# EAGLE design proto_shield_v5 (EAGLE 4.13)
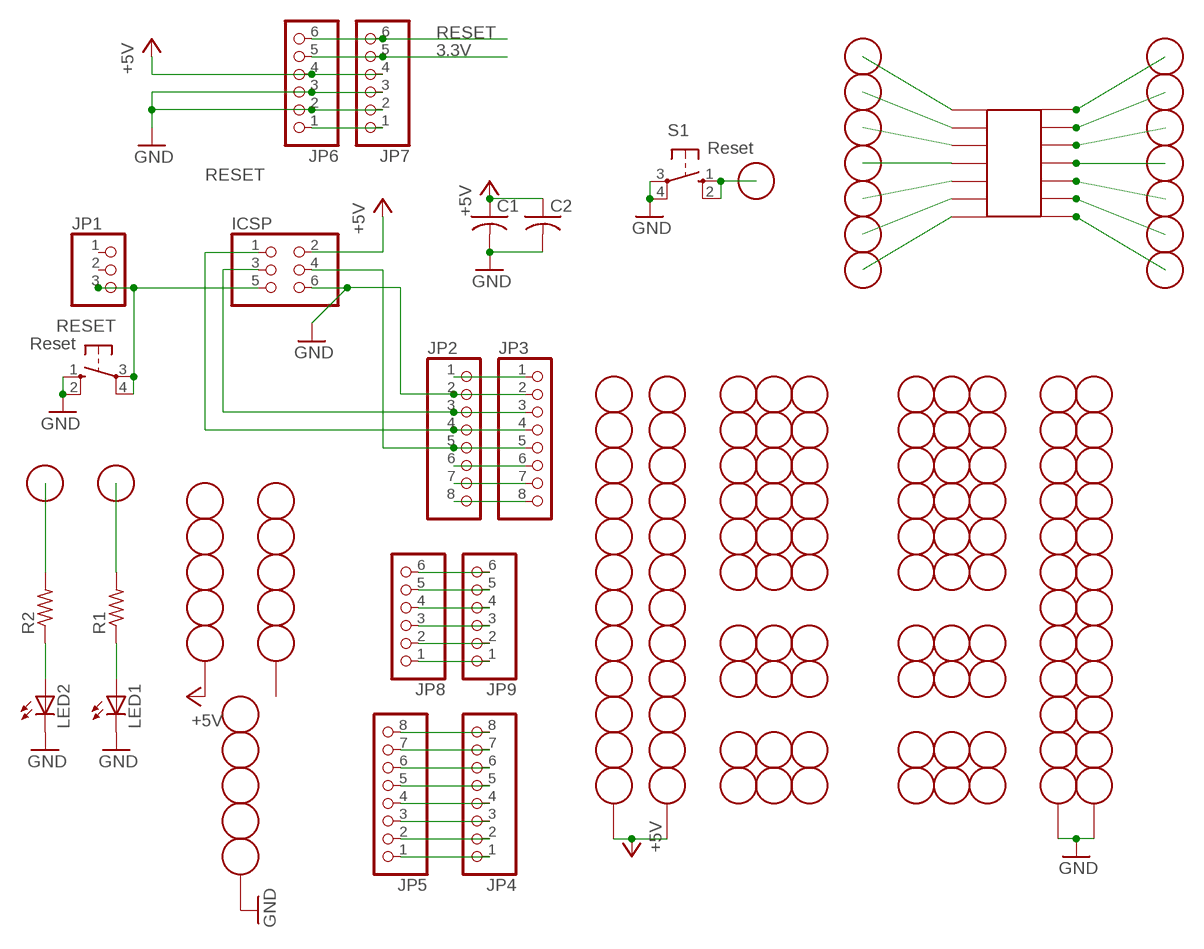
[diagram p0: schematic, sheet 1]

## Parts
C1  C-US025-025X050  [C025-025X050]
C2  C-US025-025X050  [C025-025X050]
GNDSTRIP1  12-STRIP  [12-STRIP]
GNDSTRIP2  12-STRIP  [12-STRIP]
IC1  SMD-14  [SO-14NMW]
ICSP  PINHD-2X3  [2X03]
JP1  PINHD-1X3CB  [1X03-CLEANBIG]
JP2  PINHD-1X8B  [1X08-BIG]
JP3  PINHD-1X8CLEANBIG  [1X08-CLEANBIG]
JP4  PINHD-1X8B  [1X08-BIG]
JP5  PINHD-1X8CLEANBIG  [1X08-CLEANBIG]
JP6  PINHD-1X6CB  [1X06-CLEANBIG]
JP7  PINHD-1X6B  [1X06-BIG]
JP8  PINHD-1X6CB  [1X06-CLEANBIG]
JP9  PINHD-1X6B  [1X06-BIG]
LED1  LED3MM  [LED3MM]
LED2  LED3MM  [LED3MM]
R1  R-US_0207/5V  [0207/5V]
R2  R-US_0207/5V  [0207/5V]
RESET  Reset  10-XX  [B3F-10XX]
S1  Reset  10-XX  [B3F-10XX]
U$1  5-STRIP  [5-STRIP]
U$2  PERF  [PERFHOLE]
U$4  PERF  [PERFHOLE]
U$5  3-STRIP  [3-STRIP]
U$6  PERF  [PERFHOLE]
U$7  PERF  [PERFHOLE]
U$8  PERF  [PERFHOLE]
U$9  PERF  [PERFHOLE]
U$10  3-STRIP  [3-STRIP]
U$11  3-STRIP  [3-STRIP]
U$12  3-STRIP  [3-STRIP]
U$13  3-STRIP  [3-STRIP]
U$14  3-STRIP  [3-STRIP]
U$15  3-STRIP  [3-STRIP]
U$16  PERF  [PERFHOLE]
U$17  3-STRIP  [3-STRIP]
U$18  3-STRIP  [3-STRIP]
U$19  PERF  [PERFHOLE]
U$20  3-STRIP  [3-STRIP]
U$21  3-STRIP  [3-STRIP]
U$22  3-STRIP  [3-STRIP]
U$23  3-STRIP  [3-STRIP]
U$25  PERF  [PERFHOLE]
U$26  3-STRIP  [3-STRIP]
U$27  PERF  [PERFHOLE]
U$28  3-STRIP  [3-STRIP]
U$29  3-STRIP  [3-STRIP]
U$30  3-STRIP  [3-STRIP]
U$31  3-STRIP  [3-STRIP]
U$32  3-STRIP  [3-STRIP]
U$33  3-STRIP  [3-STRIP]
U$34  PERF  [PERFHOLE]
U$35  PERF  [PERFHOLE]
U$36  5-STRIP  [5-STRIP]
U$37  PERF  [PERFHOLE]
U$38  PERF  [PERFHOLE]
U$39  PERF  [PERFHOLE]
U$40  PERF  [PERFHOLE]
U$41  PERF  [PERFHOLE]
U$42  5-STRIP  [5-STRIP]
VCCSTRIP1  12-STRIP  [12-STRIP]
VCCSTRIP2  12-STRIP  [12-STRIP]

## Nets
3.3V: JP6.5 JP7.5
+5V: C1.1 C2.1 ICSP.2 JP6.4 JP7.4 U$36.P$3 VCCSTRIP1.P$1 VCCSTRIP2.P$1
GND: C1.2 C2.2 GNDSTRIP1.P$1 GNDSTRIP2.P$1 ICSP.6 JP2.2 JP3.2 JP6.2 JP6.3 JP7.2 JP7.3 LED1.K(C) LED2.K(C) RESET.1(S) RESET.2(S1) S1.3(P) S1.4(P1) U$42.P$3
N$2: ICSP.3 JP2.3 JP3.3
N$4: ICSP.1 JP2.4 JP3.4
N$5: ICSP.4 JP2.5 JP3.5
N$8: LED1.A R1.1
N$15: JP6.1 JP7.1
N$16: R1.2 U$7.P$1
N$40: R2.2 U$4.P$1
N$41: LED2.A R2.1
N$126: IC1.P$1 U$2.P$1
N$127: IC1.P$2 U$6.P$1
N$135: JP2.8 JP3.8
N$145: JP2.7 JP3.7
N$149: IC1.P$3 U$8.P$1
N$150: IC1.P$4 U$9.P$1
N$151: IC1.P$5 U$19.P$1
N$152: JP2.6 JP3.6
N$153: JP2.1 JP3.1
N$154: JP8.1 JP9.1
N$155: IC1.P$6 U$25.P$1
N$156: IC1.P$7 U$27.P$1
N$157: IC1.P$8 U$34.P$1
N$158: IC1.P$9 U$35.P$1
N$159: IC1.P$10 U$37.P$1
N$164: JP8.2 JP9.2
N$165: IC1.P$11 U$38.P$1
N$166: IC1.P$12 U$39.P$1
N$167: IC1.P$13 U$40.P$1
N$178: IC1.P$14 U$41.P$1
N$181: JP8.3 JP9.3
N$182: JP8.4 JP9.4
N$183: JP8.5 JP9.5
N$184: JP8.6 JP9.6
N$185: JP4.1 JP5.1
N$186: JP4.2 JP5.2
N$187: JP4.3 JP5.3
N$188: JP4.4 JP5.4
N$189: JP4.5 JP5.5
N$190: JP4.6 JP5.6
N$191: JP4.7 JP5.7
N$192: JP4.8 JP5.8
N$194: S1.1(S) S1.2(S1) U$16.P$1
RESET: ICSP.5 JP1.3 JP6.6 JP7.6 RESET.3(P) RESET.4(P1)
Unconnected: JP1.1 JP1.2 U$1.P$3

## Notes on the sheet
- RESET

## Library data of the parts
C1 C2 = rcl-ez:C-US: CAPACITOR, American symbol
GNDSTRIP1 GNDSTRIP2 VCCSTRIP1 VCCSTRIP2 = Atmex:12-STRIP
IC1 = carduino:SMD-14
ICSP = pinhead:PINHD-2X3: PIN HEADER
JP1 = carduino:PINHD-1X3: PIN HEADER
JP2-JP5 = carduino:PINHD-1X8: PIN HEADER
JP6-JP9 = carduino:PINHD-1X6: PIN HEADER
LED1 LED2 = minimidi:LED: LED
R1 R2 = rcl-ez:R-US_: RESISTOR, American symbol
RESET S1 = switch-omron:10-XX: OMRON SWITCH
U$1 U$36 U$42 = Atmex:5-STRIP
U$2 U$4 U$6-U$9 U$16 U$19 U$25 U$27 U$34 U$35 U$37-U$41 = carduino:PERF
U$5 U$10-U$15 U$17 U$18 U$20-U$23 U$26 U$28-U$33 = Atmex:3-STRIP

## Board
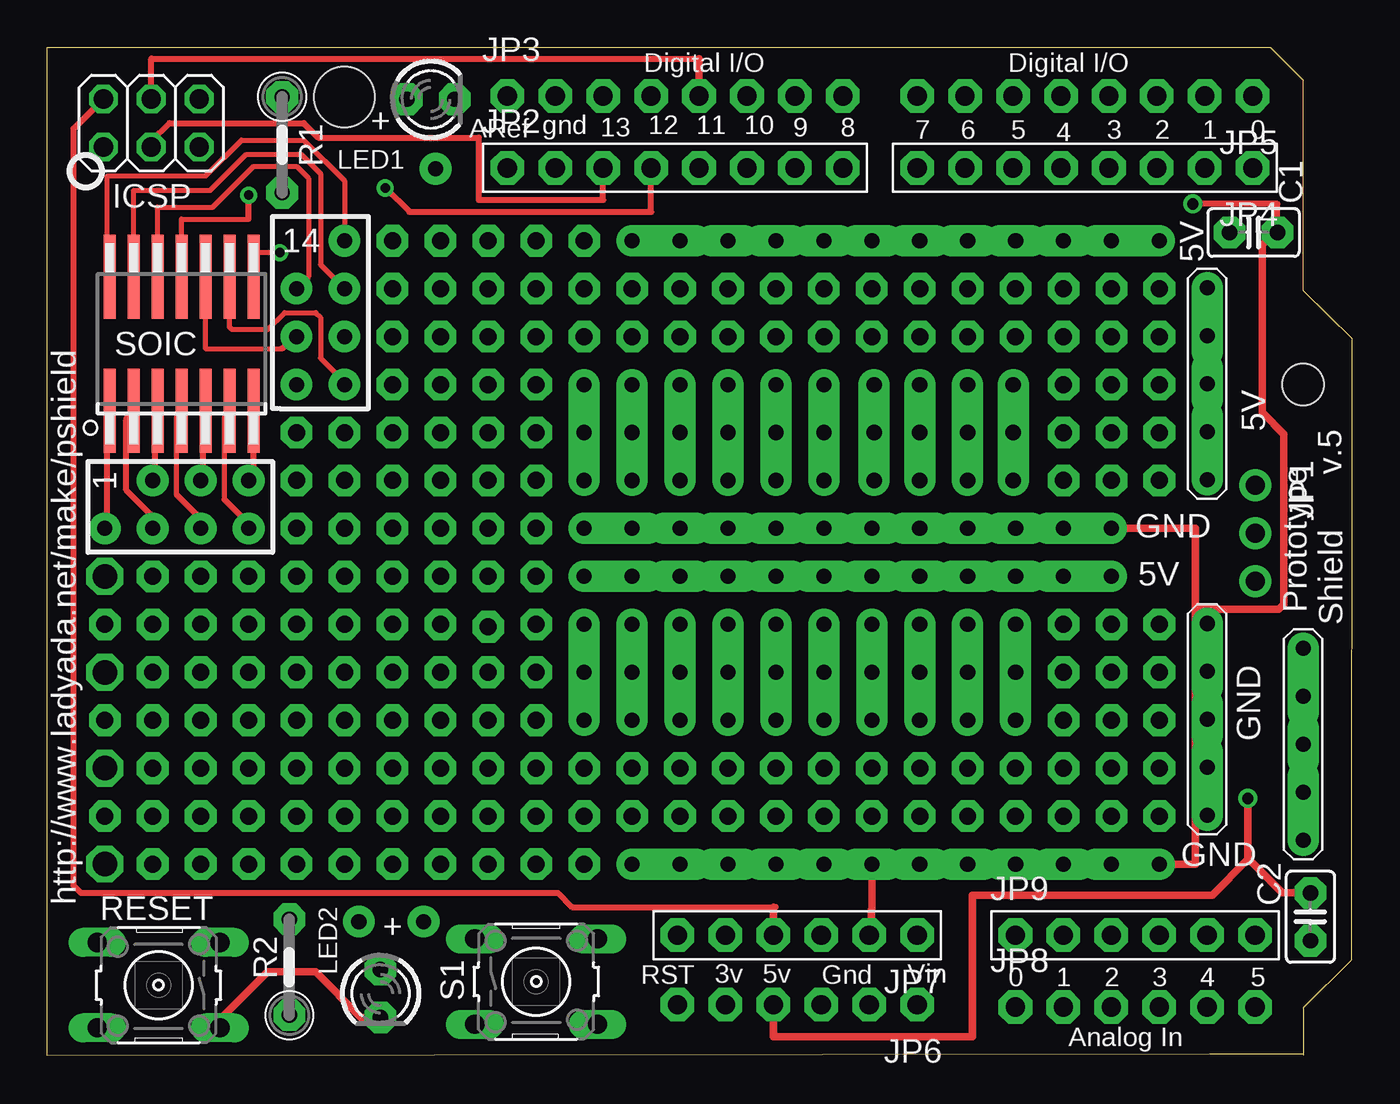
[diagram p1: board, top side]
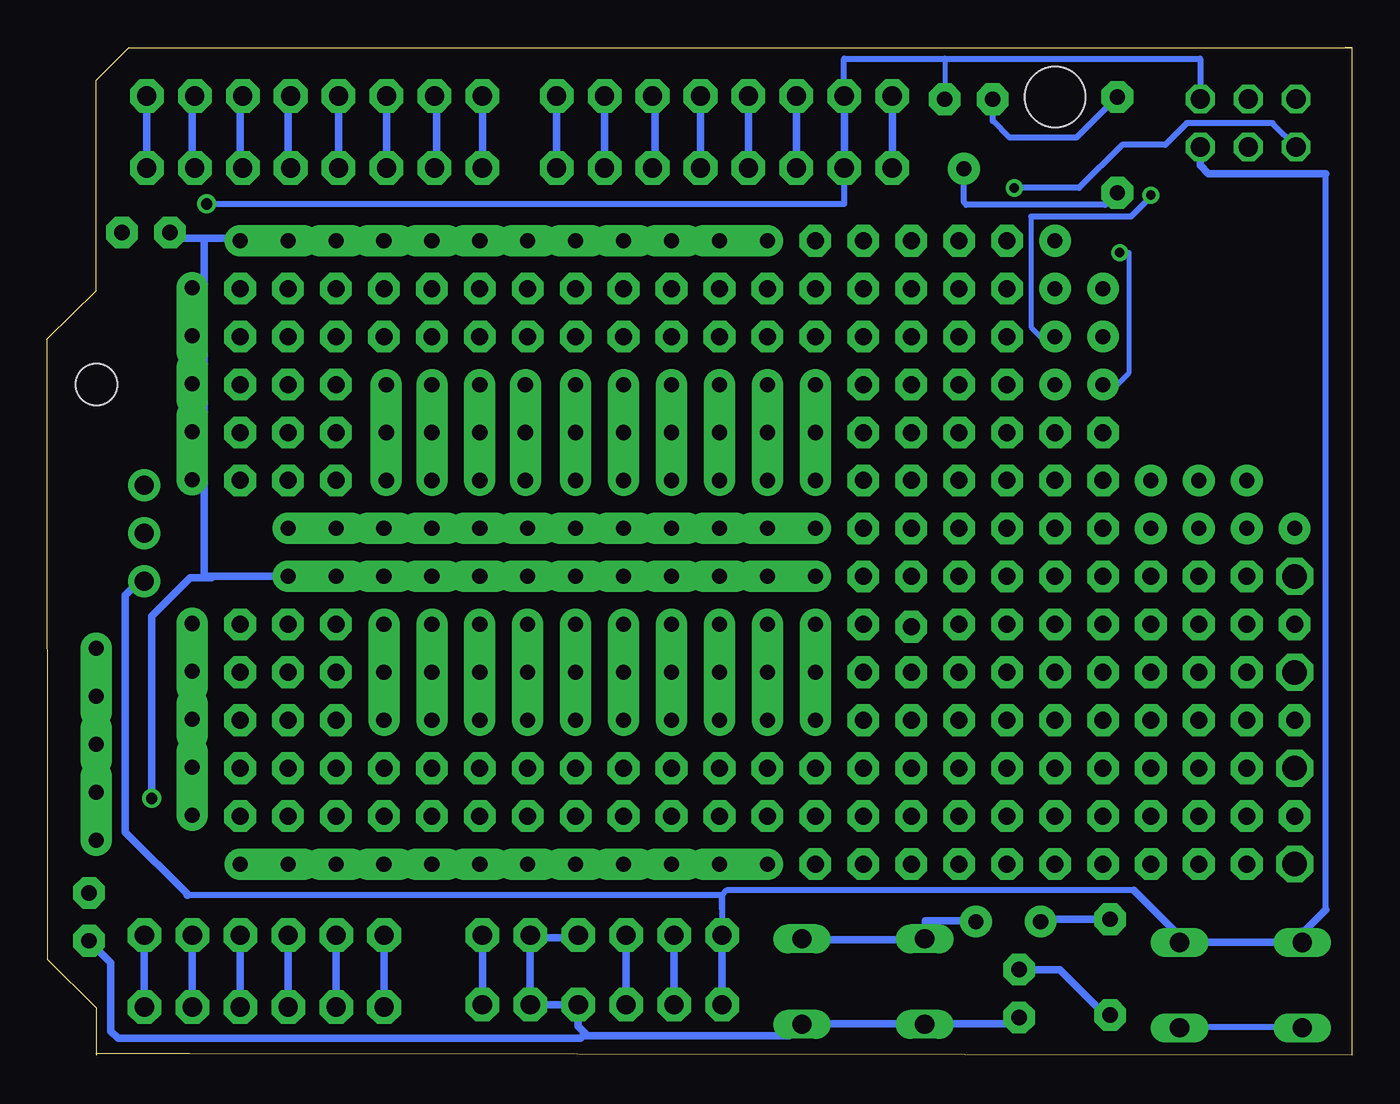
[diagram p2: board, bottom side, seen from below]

Size 69.16 x 53.39 mm. Coordinates in mm from the lower left corner, seen from the top.
Outline: 0,53.35 64.83,53.35 66.55,51.63 66.55,40.49 69.16,37.95 69.13,5.05
Outline: 0,53.35 0.38,53.39
Outline: 69.13,5.05 69.13,5.05
Outline: 69.13,5.05 66.55,2.5 66.57,0
Outline: 0,53.35 0,0 61.6,0.09 66.58,0.08
Copper layers (1*16): Top 0.035mm / dielectric 1.5mm / Bottom 0.035mm
Design rules "default": minimum track width 10mil, minimum drill 19mil, track to track 10mil, track to pad 10mil, pad to pad 0mil, via to via 10mil, smd to smd 0mil, copper to edge 10mil, drill to drill 8mil, minimum pad ring 10mil, minimum via ring 8mil, stop-mask expansion 4mil, vias tented up to drill 0mil, thermal gap 10mil
Holes 3.2 mm at 15.75,50.76
Holes 2.2 mm at 66.55,35.52

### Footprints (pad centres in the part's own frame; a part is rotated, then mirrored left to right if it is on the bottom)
C025-025X050 = drill 0.813 pad 1.676 octagon: 1 -1.27,0; 2 1.27,0
12-STRIP = drill 0.8 pad 1.676 offset: P$1 0,0; P$11 27.94,0 | drill 0.8 pad 1.676 long: P$2 2.54,0; P$3 5.08,0; P$4 7.62,0; P$5 10.16,0; P$6 12.7,0; P$7 15.24,0; P$8 17.78,0; P$9 20.32,0; P$10 22.86,0; P$12 25.4,0
SO-14NMW = smd 0.635 x 4.445: P$1 -3.048,-3.683; P$2 -1.778,-3.683; P$3 -0.508,-3.683; P$4 0.762,-3.683; P$5 2.032,-3.683; P$6 3.302,-3.683; P$7 4.572,-3.683; P$8 4.572,3.429; P$9 3.302,3.429; P$10 2.032,3.429; P$11 0.762,3.429; P$12 -0.508,3.429; P$13 -1.778,3.429; P$14 -3.048,3.429
2X03 = drill 1.016 octagon: 1 -2.54,-1.27; 2 -2.54,1.27; 3 0,-1.27; 4 0,1.27; 5 2.54,-1.27; 6 2.54,1.27
1X03-CLEANBIG = drill 1.016 pad 1.676 round: 1 -2.54,0; 2 0,0; 3 2.54,0
1X08-BIG = drill 1.016 pad 1.778 octagon: 1 -8.89,0; 2 -6.35,0; 3 -3.81,0; 4 -1.27,0; 5 1.27,0; 6 3.81,0; 7 6.35,0; 8 8.89,0
1X08-CLEANBIG = drill 1.016 pad 1.778 octagon: 1 -8.89,0; 2 -6.35,0; 3 -3.81,0; 4 -1.27,0; 5 1.27,0; 6 3.81,0; 7 6.35,0; 8 8.89,0
1X06-CLEANBIG = drill 1.016 pad 1.778 octagon: 1 -6.35,0; 2 -3.81,0; 3 -1.27,0; 4 1.27,0; 5 3.81,0; 6 6.35,0
1X06-BIG = drill 1.016 pad 1.778 octagon: 1 -6.35,0; 2 -3.81,0; 3 -1.27,0; 4 1.27,0; 5 3.81,0; 6 6.35,0
LED3MM = drill 0.813 pad 1.676 octagon: A -1.27,0; K 1.27,0
0207/5V = drill 0.813 pad 1.676 octagon: 1 -2.54,0; 2 2.54,0
B3F-10XX = drill 1.016 long: 1 -3.251,2.261; 2 3.251,2.261; 3 -3.251,-2.261; 4 3.251,-2.261
5-STRIP = drill 0.8 pad 1.676 long: P$1 2.54,0; P$2 5.08,0; P$5 7.62,0 | drill 0.8 pad 1.676 offset: P$3 0,0; P$4 10.16,0
PERFHOLE = drill 0.8 pad 1.676 round: P$1 0,0
3-STRIP = drill 0.8 pad 1.676 offset: 1 -2.54,0; P$5 2.54,0 | drill 0.8 pad 1.676 long: P$6 0,0

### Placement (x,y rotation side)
C1  63.92,43.58 0 top
C2  66.94,7.33 270 top
GNDSTRIP1  56.39,27.9 180 top
GNDSTRIP2  58.93,10.12 180 top
IC1  6.36,37.81 0 top
ICSP  5.52,49.38 0 top
JP1  64.01,27.65 270 top
JP2  33.27,47 0 top
JP3  33.27,50.81 0 top
JP4  54.99,47 180 top
JP5  54.99,50.81 180 top
JP6  39.75,2.67 180 top
JP7  39.75,6.36 180 top
JP8  57.65,2.55 0 top
JP9  57.65,6.36 0 top
LED1  20.33,50.63 0 top
LED2  17.66,3.26 270 top
R1  12.45,48.22 270 top
R2  12.83,4.66 90 top
RESET  5.9,3.71 180 top
S1  25.91,3.9 0 top
U$1  66.55,11.39 90 top
U$2  3.05,27.9 0 top
U$4  16.52,7.07 0 top
U$5  48.77,20.28 90 top
U$6  5.59,27.9 0 top
U$7  20.58,46.95 0 top
U$8  5.59,30.44 0 top
U$9  8.13,27.9 0 top
U$10  46.23,32.98 90 top
U$11  46.23,20.28 90 top
U$12  48.77,32.98 90 top
U$13  51.19,32.98 90 top
U$14  51.31,20.28 90 top
U$15  43.82,32.98 90 top
U$16  19.95,7.07 0 top
U$17  28.45,32.98 90 top
U$18  30.99,20.28 90 top
U$19  8.13,30.44 0 top
U$20  33.53,32.98 90 top
U$21  38.61,32.98 90 top
U$22  36.07,20.28 90 top
U$23  38.61,20.28 90 top
U$25  10.67,27.9 0 top
U$26  28.45,20.28 90 top
U$27  10.67,30.44 0 top
U$28  41.15,32.98 90 top
U$29  30.99,32.98 90 top
U$30  36.07,32.98 90 top
U$31  33.53,20.28 90 top
U$32  43.69,20.28 90 top
U$33  41.15,20.28 90 top
U$34  13.21,35.52 90 top
U$35  15.75,35.52 90 top
U$36  61.46,30.49 90 top
U$37  13.21,38.06 90 top
U$38  15.75,38.06 90 top
U$39  13.21,40.6 90 top
U$40  15.75,40.6 90 top
U$41  15.75,43.14 90 top
U$42  61.46,12.71 90 top
VCCSTRIP1  58.93,43.14 180 top
VCCSTRIP2  56.39,25.36 180 top

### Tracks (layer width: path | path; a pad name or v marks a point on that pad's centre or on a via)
3.3V
  Bottom 0.406: JP6.5 35.94,2.8 | 35.94,2.8 JP7.5 | 35.94,2.8 35.81,2.8
+5V  (via drill 0.6)
  Top 0.305: ICSP.2 1.4,49.07 1.4,8.98 1.78,8.6 27.06,8.6 27.82,7.83 38.48,7.83 38.61,7.83 | 38.49,0.98 38.48,0.99 38.48,1.28
  Top 0.406: 38.49,0.98 49.03,0.98 49.03,8.47 61.73,8.47 63.62,10.36 63.62,10.42 | JP6.4 38.48,1.28 38.48,1.11 | 38.48,7.83 JP7.4 | 63.62,10.42 v63.62,13.59 | C2.1 65.45,8.6 63.62,10.42
  Bottom 0.305: 60.84,25.36 60.84,30.49 U$36.P$3
  Bottom 0.406: 60.45,25.36 VCCSTRIP2.P$1 | 60.45,25.36 60.84,25.36 60.84,43.27 | 58.55,43.27 VCCSTRIP1.P$1 | 60.84,43.27 58.55,43.27 | 58.55,43.27 58.81,43.01 | 60.84,43.27 62.36,43.27 C1.1 | JP7.4 38.48,6.23 | 38.48,6.23 JP6.4 | 38.48,6.23 38.35,6.23 | v63.62,13.59 63.62,23.25 61.59,25.28 60.45,25.28 60.45,25.36
GND  (via drill 0.6)
  Top 0.305: 58.81,10.25 58.81,10.5 | GNDSTRIP2.P$1 58.81,10.25 | 58.81,10.25 58.81,9.74 | 60.46,45.04 60.46,45.09 v60.7,45.09 65.19,45.09 C1.2 | U$42.P$3 61.08,13.09 61.08,13.59
  Top 0.406: 59.06,10.12 59.19,10.12 | 59.19,10.12 60.84,10.12 | 59.19,10.12 59.19,9.99 | GNDSTRIP1.P$1 60.84,27.9 60.84,23.63 | LED2.K 16.64,1.99 14.23,4.4 11.69,4.4 9.15,1.86 RESET.1 | 60.46,45.04 60.84,45.04 | 60.84,10.12 60.84,23.63 | 59.06,10.12 GNDSTRIP2.P$1 | 59.06,10.12 43.69,10.12 43.69,7.71 43.68,7.7 43.68,6.48 JP7.2 | 60.84,10.12 60.84,13.59 61.08,13.59 61.16,13.59 | C1.2 65.19,43.65 65.15,43.69 64.39,42.93 64.39,34.04 65.53,32.9 65.53,23.88 65.27,23.63 60.84,23.63
  Bottom 0.254: 21.6,52.79 LED1.K
  Bottom 0.305: ICSP.6 8.06,52.79 21.6,52.79 26.93,52.79 26.93,51.01 26.86,51.01 26.8,51.01 | 2.67,1.45 2.76,1.48 9.06,1.48 RESET.1 9.31,1.99 | JP2.2 26.92,45.09 v60.7,45.09
  Bottom 0.406: 2.67,1.48 2.67,1.45 RESET.2 | 22.66,1.66 22.73,1.66 | LED2.K 17.66,1.66 22.66,1.66 | 29.17,1.66 29.21,1.66 29.84,1.02 40.51,1.02 40.57,1.08 | 29.17,1.66 S1.4 | 22.66,1.66 S1.3 | 22.66,1.66 29.17,1.66 | JP2.2 JP3.2 26.92,50.95 26.86,51.01 | 43.56,6.23 JP6.2 JP6.3 41.02,1.53 40.57,1.08 | 43.56,6.23 JP7.2 | JP7.3 41.02,6.23 43.56,6.23 | C2.2 65.78,4.9 65.78,1.28 65.4,0.89 40.89,0.89 40.76,1.02 40.64,1.02 40.57,1.08
N$1  (via drill 0.9 pad 1.68)
  other vias: 58.93,30.44
N$2
  Top 0.254: ICSP.3 5.52,48.4
  Top 0.305: 29.46,45.3 22.87,45.3 22.87,48.6 14.36,48.6 13.6,49.36 6.48,49.36 5.52,48.4 | 29.46,45.3 29.47,45.3 | 29.46,45.3 JP2.3
  Bottom 0.406: JP2.3 JP3.3
N$3  (via drill 0.9 pad 1.68)
  other vias: 13.21,32.98
N$4  (via drill 0.5 pad 0.25)
  Top 0.305: 32,44.66 19.2,44.66 17.9,45.96 | 17.9,45.96 17.9,45.94 v17.91,45.93 | 17.9,45.96 17.9,45.98 | 32,44.66 32.01,44.66 | 32,44.66 JP2.4
  Bottom 0.305: ICSP.1 4.23,49.36 8.77,49.36 9.91,48.22 12.2,48.22 14.48,45.93 v17.91,45.93
  Bottom 0.406: JP2.4 JP3.4
N$5
  Top 0.305: ICSP.4 5.52,52.79 34.55,52.79
  Top 0.406: 34.55,52.79 34.54,52.78 JP3.5
  Bottom 0.406: JP3.5 JP2.5
N$6  (via drill 0.9 pad 1.68)
  other vias: 13.21,30.44
N$7  (via drill 0.9 pad 1.68)
  other vias: 13.21,27.9
N$8
  Bottom 0.305: R1.1 14.61,48.6 18.17,48.6 19.06,49.49 LED1.A 19.06,50.89
N$9  (via drill 1.3)
  other vias: 3.05,25.36
N$10  (via drill 0.9 pad 1.68)
  other vias: 3.05,22.82
N$11  (via drill 0.9 pad 1.68)
  other vias: 36.07,12.66
N$12  (via drill 0.9 pad 1.68)
  other vias: 36.07,15.2
N$13  (via drill 0.9 pad 1.68)
  other vias: 36.07,38.06
N$14  (via drill 0.9 pad 1.68)
  other vias: 36.07,40.6
N$15
  Bottom 0.406: JP6.1 JP7.1
N$16
  Bottom 0.305: R1.2 13.09,45.04 20.45,45.04 20.58,45.17 U$7.P$1
N$17  (via drill 0.9 pad 1.68)
  other vias: 8.13,25.36
N$18  (via drill 0.9 pad 1.68)
  other vias: 8.13,22.82
N$19  (via drill 0.9 pad 1.68)
  other vias: 8.13,20.28
N$20  (via drill 0.9 pad 1.68)
  other vias: 25.91,10.12
N$21  (via drill 0.9 pad 1.68)
  other vias: 23.37,10.12
N$22  (via drill 0.9 pad 1.68)
  other vias: 28.45,10.12
N$23  (via drill 0.9 pad 1.68)
  other vias: 8.13,10.12
N$24  (via drill 0.9 pad 1.68)
  other vias: 10.67,10.12
N$25  (via drill 0.9 pad 1.68)
  other vias: 23.37,30.44
N$26  (via drill 0.9 pad 1.68)
  other vias: 23.37,32.98
N$27  (via drill 0.9 pad 1.68)
  other vias: 23.37,35.52
N$28  (via drill 0.9 pad 1.68)
  other vias: 25.91,30.44
N$29  (via drill 0.9 pad 1.68)
  other vias: 25.91,32.98
N$30  (via drill 0.9 pad 1.68)
  other vias: 33.53,12.66
N$31  (via drill 0.9 pad 1.68)
  other vias: 33.53,15.2
N$32  (via drill 0.9 pad 1.68)
  other vias: 33.53,38.06
N$33  (via drill 0.9 pad 1.68)
  other vias: 33.53,40.6
N$34  (via drill 0.9 pad 1.68)
  other vias: 18.29,10.12
N$35  (via drill 0.9 pad 1.68)
  other vias: 25.91,35.52
N$36  (via drill 0.9 pad 1.68)
  other vias: 23.37,17.74
N$37  (via drill 0.9 pad 1.68)
  other vias: 23.37,20.28
N$38  (via drill 0.9 pad 1.68)
  other vias: 10.67,22.82
N$39  (via drill 0.9 pad 1.68)
  other vias: 10.67,25.36
N$40
  Bottom 0.406: U$4.P$1 16.52,7.2 R2.2
N$41
  Bottom 0.406: R2.1 12.96,1.99 15.5,4.53 LED2.A
N$42  (via drill 1.3)
  other vias: 3.05,20.28
N$43  (via drill 0.9 pad 1.68)
  other vias: 5.59,22.82
N$44  (via drill 0.9 pad 1.68)
  other vias: 5.59,25.36
N$46  (via drill 0.9 pad 1.68)
  other vias: 38.61,12.66
N$47  (via drill 0.9 pad 1.68)
  other vias: 38.61,15.2
N$48  (via drill 0.9 pad 1.68)
  other vias: 10.67,20.28
N$49  (via drill 0.9 pad 1.68)
  other vias: 20.83,10.12
N$50  (via drill 0.9 pad 1.68)
  other vias: 13.21,10.12
N$51  (via drill 0.9 pad 1.68)
  other vias: 13.21,20.28
N$52  (via drill 0.9 pad 1.68)
  other vias: 13.21,22.82
N$53  (via drill 0.9 pad 1.68)
  other vias: 13.21,25.36
N$60  (via drill 0.9 pad 1.68)
  other vias: 41.15,12.66
N$61  (via drill 0.9 pad 1.68)
  other vias: 15.75,10.12
N$62  (via drill 0.9 pad 1.68)
  other vias: 25.91,43.14
N$63  (via drill 0.9 pad 1.68)
  other vias: 23.37,43.14
N$64  (via drill 0.9 pad 1.68)
  other vias: 41.15,15.2
N$65  (via drill 0.9 pad 1.68)
  other vias: 41.15,38.06
N$66  (via drill 0.9 pad 1.68)
  other vias: 41.15,40.6
N$67  (via drill 0.9 pad 1.68)
  other vias: 28.45,43.14
N$68  (via drill 0.9 pad 1.68)
  other vias: 38.61,38.06
N$69  (via drill 0.9 pad 1.68)
  other vias: 38.61,40.6
N$71  (via drill 0.9 pad 1.68)
  other vias: 18.29,30.44
N$72  (via drill 0.9 pad 1.68)
  other vias: 18.29,32.98
N$73  (via drill 0.9 pad 1.68)
  other vias: 18.29,35.52
N$74  (via drill 0.9 pad 1.68)
  other vias: 18.29,38.06
N$75  (via drill 0.9 pad 1.68)
  other vias: 18.29,40.6
N$76  (via drill 0.9 pad 1.68)
  other vias: 46.23,12.66
N$77  (via drill 0.9 pad 1.68)
  other vias: 46.23,15.2
N$78  (via drill 0.9 pad 1.68)
  other vias: 46.23,38.06
N$79  (via drill 0.9 pad 1.68)
  other vias: 46.23,40.6
N$80  (via drill 0.9 pad 1.68)
  other vias: 5.59,20.28
N$81  (via drill 0.9 pad 1.68)
  other vias: 18.29,27.9
N$82  (via drill 0.9 pad 1.68)
  other vias: 18.29,25.36
N$83  (via drill 0.9 pad 1.68)
  other vias: 18.29,22.82
N$84  (via drill 0.9 pad 1.68)
  other vias: 18.29,20.28
N$85  (via drill 0.9 pad 1.68)
  other vias: 18.29,43.14
N$86  (via drill 0.9 pad 1.68)
  other vias: 20.83,43.14
N$87  (via drill 0.9 pad 1.68)
  other vias: 23.37,22.69
N$90  (via drill 0.9 pad 1.68)
  other vias: 15.75,30.44
N$91  (via drill 0.9 pad 1.68)
  other vias: 15.75,32.98
N$95  (via drill 0.9 pad 1.68)
  other vias: 43.69,12.66
N$96  (via drill 0.9 pad 1.68)
  other vias: 43.69,15.2
N$97  (via drill 0.9 pad 1.68)
  other vias: 43.69,38.06
N$98  (via drill 0.9 pad 1.68)
  other vias: 43.69,40.6
N$99  (via drill 0.9 pad 1.68)
  other vias: 15.75,20.28
N$100  (via drill 0.9 pad 1.68)
  other vias: 15.75,27.9
N$101  (via drill 0.9 pad 1.68)
  other vias: 15.75,25.36
N$102  (via drill 0.9 pad 1.68)
  other vias: 15.75,22.82
N$103  (via drill 0.9 pad 1.68)
  other vias: 20.83,22.82
N$104  (via drill 0.9 pad 1.68)
  other vias: 20.83,25.36
N$105  (via drill 0.9 pad 1.68)
  other vias: 20.83,27.9
N$106  (via drill 0.9 pad 1.68)
  other vias: 20.83,30.44
N$107  (via drill 0.9 pad 1.68)
  other vias: 20.83,32.98
N$108  (via drill 0.9 pad 1.68)
  other vias: 20.83,35.52
N$109  (via drill 0.9 pad 1.68)
  other vias: 20.83,38.06
N$110  (via drill 0.9 pad 1.68)
  other vias: 20.83,40.6
N$111  (via drill 0.9 pad 1.68)
  other vias: 48.77,12.66
N$112  (via drill 0.9 pad 1.68)
  other vias: 48.77,15.2
N$113  (via drill 0.9 pad 1.68)
  other vias: 20.83,20.28
N$114  (via drill 0.9 pad 1.68)
  other vias: 3.05,17.74
N$118  (via drill 1.3 pad 1.68)
  other vias: 3.05,15.2
N$119  (via drill 0.9 pad 1.68)
  other vias: 3.05,12.66
N$120  (via drill 0.9 pad 1.68)
  other vias: 5.59,15.2
N$121  (via drill 0.9 pad 1.68)
  other vias: 5.59,17.74
N$122  (via drill 0.9 pad 1.68)
  other vias: 5.59,12.66
N$123  (via drill 1.3)
  other vias: 3.05,10.12
N$124  (via drill 0.9 pad 1.68)
  other vias: 5.59,10.12
N$125  (via drill 0.9 pad 1.68)
  other vias: 51.31,12.66
N$126
  Top 0.305: U$2.P$1 3.18,27.9 3.18,33.89 arc-45 3.26,34.07 IC1.P$1
N$127
  Top 0.305: IC1.P$2 4.27,33.82 arc45 4.2,33.64 4.2,29.93 5.52,28.61 arc-45 5.59,28.43 U$6.P$1
N$128  (via drill 0.9 pad 1.68)
  other vias: 58.93,32.98
N$129  (via drill 0.9 pad 1.68)
  other vias: 51.31,15.2
N$130  (via drill 0.9 pad 1.68)
  other vias: 51.31,38.06
N$131  (via drill 0.9 pad 1.68)
  other vias: 51.31,40.6
N$132  (via drill 0.9 pad 1.68)
  other vias: 58.93,35.52
N$133  (via drill 0.9 pad 1.68)
  other vias: 48.77,38.06
N$134  (via drill 0.9 pad 1.68)
  other vias: 48.77,40.6
N$135
  Bottom 0.406: JP2.8 JP3.8
N$136  (via drill 0.9 pad 1.68)
  other vias: 58.93,17.74
N$137  (via drill 0.9 pad 1.68)
  other vias: 58.93,20.28
N$138  (via drill 0.9 pad 1.68)
  other vias: 53.85,30.44
N$139  (via drill 0.9 pad 1.68)
  other vias: 53.85,32.98
N$140  (via drill 0.9 pad 1.68)
  other vias: 53.85,35.52
N$141  (via drill 0.9 pad 1.68)
  other vias: 56.39,12.66
N$142  (via drill 0.9 pad 1.68)
  other vias: 56.39,15.2
N$143  (via drill 0.9 pad 1.68)
  other vias: 56.39,38.06
N$144  (via drill 0.9 pad 1.68)
  other vias: 56.39,40.6
N$145
  Bottom 0.406: JP2.7 JP3.7
N$146  (via drill 0.9 pad 1.68)
  other vias: 53.85,22.82
N$147  (via drill 0.9 pad 1.68)
  other vias: 53.85,20.28
N$148  (via drill 0.9 pad 1.68)
  other vias: 53.85,17.74
N$149
  Top 0.305: U$8.P$1 5.72,30.44 5.72,33.89 arc-45 5.8,34.07 IC1.P$3
N$150
  Top 0.254: 6.94,33.94 arc45 6.86,33.76 6.86,29.68
  Top 0.305: 6.94,33.94 IC1.P$4 | 6.86,29.68 8.06,28.48 arc-45 8.13,28.3 U$9.P$1
N$151
  Top 0.305: U$19.P$1 8.26,30.44 8.26,33.89 arc-45 8.34,34.07 IC1.P$5
N$152
  Bottom 0.406: JP3.6 36.95,50.81 36.95,47 JP2.6
N$153
  Bottom 0.406: JP2.1 JP3.1
N$154
  Bottom 0.406: JP8.1 JP9.1
N$155
  Top 0.254: IC1.P$6 9.48,33.94 arc45 9.4,33.76 9.4,29.42
  Top 0.305: 9.4,29.42 10.6,28.23 arc-45 10.67,28.05 U$25.P$1
N$156
  Top 0.254: 10.88,30.37 10.93,30.31
  Top 0.305: 10.88,30.37 arc45 10.7,30.44 U$27.P$1 | 10.93,30.31 IC1.P$7
N$157  (via drill 0.5)
  Top 0.254: IC1.P$8 10.93,42.5 v12.33,42.5
  Bottom 0.254: v12.33,42.5 11.82,42.5 11.82,36.15 12.45,35.52 U$34.P$1 13.34,35.52
N$158
  Top 0.254: IC1.P$9 9.66,38.57 9.79,38.44 11.69,38.44 12.58,39.33 14.23,39.33 14.48,39.08 14.48,36.92 15.75,35.65 15.88,35.65 U$35.P$1
N$159
  Top 0.254: IC1.P$10 8.39,37.42 12.44,37.42
  Top 0.305: 13.26,38.11 13.33,38.11 | 13.26,38.11 U$37.P$1 | 12.44,37.42 13.12,38.11 13.26,38.11
N$160  (via drill 0.9 pad 1.68)
  other vias: 53.85,12.66
N$161  (via drill 0.9 pad 1.68)
  other vias: 53.85,15.2
N$162  (via drill 0.9 pad 1.68)
  other vias: 53.85,38.06
N$163  (via drill 0.9 pad 1.68)
  other vias: 53.85,40.6
N$164
  Bottom 0.406: JP8.2 JP9.2
N$165  (via drill 0.5)
  Top 0.254: IC1.P$11 7.12,44.28 10.67,44.28
  Top 0.305: 10.67,45.59 v10.67,45.55 | 10.67,44.28 10.67,45.59 | 10.67,45.59 10.66,45.6
  Bottom 0.254: v10.67,45.55 10.66,45.55 10.66,45.47 | 17.02,44.41 17.02,38.57 16.52,38.06 U$38.P$1
  Bottom 0.305: v10.67,45.55 10.67,45.48 10.66,45.47 11.73,44.41 17.02,44.41
N$166
  Top 0.254: IC1.P$12 5.85,44.92 8.77,44.92 10.93,47.08 13.21,47.08 13.85,46.44 13.85,41.23 U$39.P$1
N$167
  Top 0.254: IC1.P$13 4.58,45.81 8.64,45.81 10.55,47.71 13.47,47.71 14.48,46.7 14.48,41.87 U$40.P$1 | U$40.P$1 15.88,40.6 | U$40.P$1
N$168  (via drill 0.9 pad 1.68)
  other vias: 56.39,17.74
N$169  (via drill 0.9 pad 1.68)
  other vias: 56.39,20.28
N$170  (via drill 0.9 pad 1.68)
  other vias: 56.39,22.82
N$171  (via drill 0.9 pad 1.68)
  other vias: 58.93,22.82
N$172  (via drill 0.9 pad 1.68)
  other vias: 25.91,27.9
N$173  (via drill 0.9 pad 1.68)
  other vias: 56.39,30.44
N$174  (via drill 0.9 pad 1.68)
  other vias: 56.39,32.98
N$175  (via drill 0.9 pad 1.68)
  other vias: 56.39,35.52
N$176  (via drill 0.9 pad 1.68)
  other vias: 58.93,12.66
N$177  (via drill 0.9 pad 1.68)
  other vias: 58.93,15.2
N$178
  Top 0.254: U$41.P$1 15.75,46.31 13.6,48.47 10.29,48.47 8.39,46.57 3.18,46.57 3.18,41.23 IC1.P$14
N$181
  Bottom 0.406: 56.38,6.61 JP9.3 | JP8.3 56.38,6.61 | 56.38,6.61 56.13,6.61
N$182
  Bottom 0.406: 58.92,6.23 JP9.4 | JP8.4 58.92,6.23 | 58.92,6.23 58.8,6.23
N$183
  Bottom 0.406: 61.46,6.48 JP9.5 | JP8.5 61.46,6.48 | 61.46,6.48 61.59,6.48
N$184
  Bottom 0.406: JP8.6 JP9.6
N$185
  Bottom 0.406: JP4.1 JP5.1
N$186
  Bottom 0.406: 61.46,50.81 61.46,50.93 | 61.46,50.81 JP5.2 | JP4.2 61.46,47 61.46,50.81
N$187
  Bottom 0.406: JP5.3 58.92,50.81 58.92,47 JP4.3
N$188
  Bottom 0.406: 56.38,50.81 56.38,51.06 | 56.38,50.81 JP5.4 | JP4.4 56.38,47 56.38,50.81
N$189
  Bottom 0.406: JP4.5 JP5.5
N$190
  Bottom 0.406: 51.18,50.93 JP5.6 JP4.6
N$191
  Bottom 0.406: 48.51,50.81 48.51,50.93 | 48.51,50.81 JP5.7 | JP4.7 48.51,47 48.51,50.81
N$192
  Bottom 0.406: 46.1,51.19 JP5.8 JP4.8
N$193  (via drill 0.9 pad 1.68)
  other vias: 25.91,25.36
N$194
  Bottom 0.305: 22.61,6.11 22.6,6.1 | 22.61,6.16 22.61,6.11 | 22.74,6.44 22.74,6.24 22.61,6.11
  Bottom 0.406: S1.2 29.17,6.1 22.66,6.1 S1.1 22.61,6.16 22.61,7.12 19.95,7.12 | 19.95,7.12 19.94,7.12 | U$16.P$1 19.95,7.12
N$195  (via drill 0.9 pad 1.68)
  other vias: 23.37,27.9
N$196  (via drill 0.9 pad 1.68)
  other vias: 23.37,25.36
N$198  (via drill 0.9 pad 1.68)
  other vias: 58.93,38.06
N$199  (via drill 0.9 pad 1.68)
  other vias: 58.93,40.6
N$206  (via drill 0.9 pad 1.68)
  other vias: 25.91,12.66
N$207  (via drill 0.9 pad 1.68)
  other vias: 25.91,15.2
N$208  (via drill 0.9 pad 1.68)
  other vias: 25.91,38.06
N$209  (via drill 0.9 pad 1.68)
  other vias: 25.91,40.6
N$210  (via drill 0.9 pad 1.68)
  other vias: 8.13,17.74
N$214  (via drill 0.9 pad 1.68)
  other vias: 8.13,15.2
N$215  (via drill 0.9 pad 1.68)
  other vias: 8.13,12.66
N$216  (via drill 0.9 pad 1.68)
  other vias: 25.91,17.74
N$217  (via drill 0.9 pad 1.68)
  other vias: 25.91,20.28
N$218  (via drill 0.9 pad 1.68)
  other vias: 10.67,15.2
N$219  (via drill 0.9 pad 1.68)
  other vias: 10.67,17.74
N$225  (via drill 0.9 pad 1.68)
  other vias: 23.37,12.66
N$226  (via drill 0.9 pad 1.68)
  other vias: 23.37,15.2
N$227  (via drill 0.9 pad 1.68)
  other vias: 23.37,38.06
N$228  (via drill 0.9 pad 1.68)
  other vias: 23.37,40.6
N$229  (via drill 0.9 pad 1.68)
  other vias: 10.67,12.66
N$241  (via drill 0.9 pad 1.68)
  other vias: 28.45,12.66
N$242  (via drill 0.9 pad 1.68)
  other vias: 28.45,15.2
N$255  (via drill 0.9 pad 1.68)
  other vias: 30.99,12.66
N$258  (via drill 0.9 pad 1.68)
  other vias: 13.21,15.2
N$259  (via drill 0.9 pad 1.68)
  other vias: 30.99,15.2
N$260  (via drill 0.9 pad 1.68)
  other vias: 30.99,38.06
N$261  (via drill 0.9 pad 1.68)
  other vias: 30.99,40.6
N$262  (via drill 0.9 pad 1.68)
  other vias: 13.21,17.74
N$263  (via drill 0.9 pad 1.68)
  other vias: 28.45,38.06
N$264  (via drill 0.9 pad 1.68)
  other vias: 28.45,40.6
N$265  (via drill 0.9 pad 1.68)
  other vias: 18.29,17.74
N$266  (via drill 0.9 pad 1.68)
  other vias: 18.29,15.2
N$267  (via drill 0.9 pad 1.68)
  other vias: 18.29,12.66
N$268  (via drill 0.9 pad 1.68)
  other vias: 15.75,17.74
N$269  (via drill 0.9 pad 1.68)
  other vias: 15.75,15.2
N$270  (via drill 0.9 pad 1.68)
  other vias: 20.83,15.2
N$271  (via drill 0.9 pad 1.68)
  other vias: 20.83,17.74
N$272  (via drill 0.9 pad 1.68)
  other vias: 20.83,12.66
N$273  (via drill 0.9 pad 1.68)
  other vias: 25.91,22.82
N$274  (via drill 0.9 pad 1.68)
  other vias: 13.21,12.66
N$275  (via drill 0.9 pad 1.68)
  other vias: 15.75,12.66
RESET
  Bottom 0.305: 11.56,8.72 33.15,8.72 33.4,8.48 33.4,8.39 | 64.01,25.36 JP1.3 | 61.73,8.47 33.41,8.47 33.4,7.72 33.4,8.39 | 1.4,7.71 1.4,46.7 | 33.41,6.82 33.4,6.83 33.4,8.39
  Bottom 0.406: 3.31,5.97 RESET.4 2.65,6.46 1.4,7.71 | 3.31,5.97 RESET.3 9.19,6.35 11.56,8.72 | 3.31,5.97 2.67,6.56 | ICSP.5 8.06,47.13 7.63,46.7 1.4,46.7 | 33.4,6.23 JP7.6 33.4,6.83 | 33.4,6.23 JP6.6 | 33.4,6.23 33.52,6.23 | 64.01,25.36 65.02,24.35 65.02,11.82 61.72,8.51 61.72,8.48 61.73,8.47

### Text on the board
tPlace: Digital I/O | Digital I/O | ARef | gnd | 13 | 12 | 11 | 10 | 9 | 8 | 7 | 6 | 5 | 3 | 2 | 1 | 0 | + | 4 | 5V | 14 | SOIC | 5V | v.5 | 1 | GND | 5V | Prototype | Shield | GND | GND | http://www.ladyada.net/make/pshield | + | RST | 3v | 5v | Vin | Gnd | 0 | 1 | 2 | 3 | 4 | 5 | Analog In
